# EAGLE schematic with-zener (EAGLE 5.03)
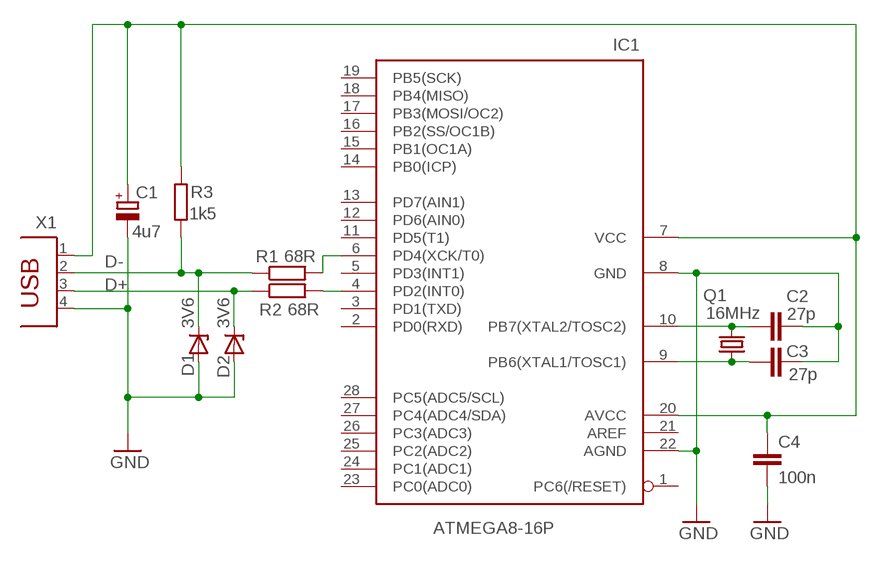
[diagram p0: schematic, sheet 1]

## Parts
C1  4u7  CPOL-EUE2-5  [E2-5]
C2  27p  C-EU025-024X044  [C025-024X044]
C3  27p  C-EU025-024X044  [C025-024X044]
C4  100n  C-EU025-024X044  [C025-024X044]
D1  3V6  ZENER-DIODEDO34-7  [DO34Z7]
D2  3V6  ZENER-DIODEDO34-7  [DO34Z7]
IC1  ATMEGA8-16P  [DIL28-3]
Q1  16MHz  CRYTALHC49U-V  [HC49U-V]
R1  68R  R-EU_0207/10  [0207/10]
R2  68R  R-EU_0207/10  [0207/10]
R3  1k5  R-EU_0207/10  [0207/10]
X1  PN61729  [PN61729]

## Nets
D+: D2.C R2.1 X1.3
D-: D1.C R1.1 R3.1 X1.2
GND: C1.- C2.2 C3.2 C4.2 D1.A D2.A IC1.8(GND) IC1.22(AGND) X1.4
N$1: IC1.6(PD4(XCK/T0)) R1.2
N$2: IC1.4(PD2(INT0)) R2.2
N$9: C3.1 IC1.9(PB6(XTAL1/TOSC1)) Q1.1
N$10: C2.1 IC1.10(PB7(XTAL2/TOSC2)) Q1.2
VCC: C1.+ C4.1 IC1.7(VCC) IC1.20(AVCC) R3.2 X1.1
Unconnected: IC1.1(PC6(/RESET)) IC1.2(PD0(RXD)) IC1.3(PD1(TXD)) IC1.5(PD3(INT1)) IC1.11(PD5(T1)) IC1.12(PD6(AIN0)) IC1.13(PD7(AIN1)) IC1.14(PB0(ICP)) IC1.15(PB1(OC1A)) IC1.16(PB2(SS/OC1B)) IC1.17(PB3(MOSI/OC2)) IC1.18(PB4(MISO)) IC1.19(PB5(SCK)) IC1.21(AREF) IC1.23(PC0(ADC0)) IC1.24(PC1(ADC1)) IC1.25(PC2(ADC2)) IC1.26(PC3(ADC3)) IC1.27(PC4(ADC4/SDA)) IC1.28(PC5(ADC5/SCL))

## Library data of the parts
C1 = rcl:CPOL-EU: POLARIZED CAPACITOR, European symbol
C2-C4 = rcl:C-EU: CAPACITOR, European symbol
D1 D2 = diode:ZENER-DIODE: Z-Diode
IC1 = avr:ATMEGA8*P: MICROCONTROLLER 8 Kbytes FLASH 1 kbytes SRAM 512 bytes EEPROM USART 4-channel 10 bit ADC 2-channel 8 bit ADC
Q1 = crystal:CRYTAL: CRYSTAL
R1-R3 = rcl:R-EU_: RESISTOR, European symbol
X1 = con-berg:PN61729: BERG USB connector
